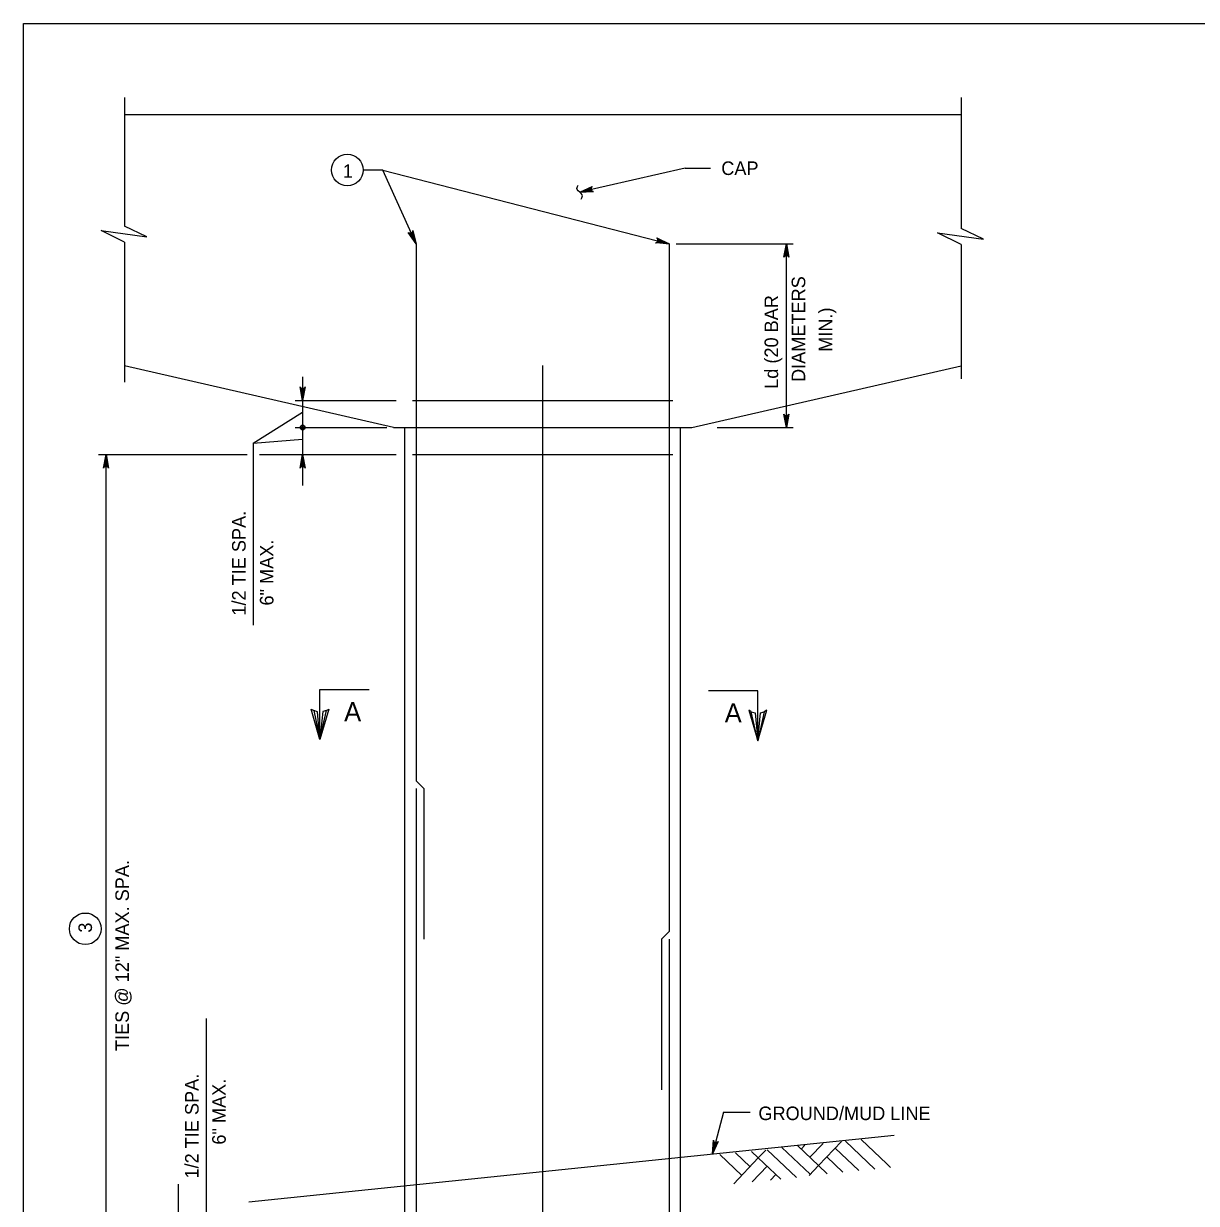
# Model space of a CAD drawing. Extents: x 646165 to 651486, y 296916 to 299292.
# Drawn here: x 649829.6 to 650089.2, y 297234.1 to 297495.3 of the extents above; entities that cross this region are included whole.
import ezdxf

# ---------------------------------------------------------------- set-up
doc = ezdxf.new("R2010")
doc.units = 0
for name, color, linetype in [('1', 7, 'Continuous'), ('2', 7, 'Continuous'), ('50', 7, 'Continuous'), ('51', 7, 'Continuous'), ('52', 7, 'Continuous'), ('53', 7, 'Continuous'), ('54', 7, 'Continuous'), ('56', 7, 'Continuous')]:
    doc.layers.add(name, color=color, linetype=linetype)

msp = doc.modelspace()

# ---------------------------------------------------------------- linework, layer by layer
at = {"layer": '1'}
for p, q in [((649895.19, 297347.84), (649906.11, 297347.84)), ((649895.19, 297336.77), (649895.19, 297347.84)), ((649992.13, 297347.58), (649981.21, 297347.58)), ((649992.13, 297336.51), (649992.13, 297347.58))]:
    msp.add_line(p, q, dxfattribs=at)
for points in [[(649896.66, 297343.19), (649895.81, 297342.96), (649895.19, 297336.77), (649896.66, 297343.19), (649897.18, 297343.52), (649895.19, 297336.77), (649894.63, 297342.95), (649893.8, 297343.18), (649895.19, 297336.77), (649893.24, 297343.52), (649893.8, 297343.18)], [(649990.66, 297342.93), (649991.51, 297342.69), (649992.13, 297336.51), (649990.66, 297342.93), (649990.14, 297343.26), (649992.13, 297336.51), (649992.69, 297342.68), (649993.52, 297342.91), (649992.13, 297336.51), (649994.08, 297343.26), (649993.52, 297342.91)]]:
    msp.add_lwpolyline(points, dxfattribs=at)
at = {"layer": '2'}
for p, q in [((649829.59, 296931.25), (649829.59, 297495.25)), ((649829.59, 297495.25), (650615.59, 297495.25))]:
    msp.add_line(p, q, dxfattribs=at)
at = {"layer": '50'}
msp.add_line((649944.48, 297040.08), (649944.48, 297419.54), dxfattribs=at)
at = {"layer": '51'}
for p, q in [((649851.93, 297475.16), (650037.08, 297475.16)), ((649911.47, 297405.84), (649851.93, 297419.49)), ((649977.48, 297405.84), (650037.08, 297419.51)), ((649911.47, 297405.84), (649977.48, 297405.84)), ((649913.98, 297224.79), (649913.98, 297405.84)), ((649974.98, 297224.79), (649974.98, 297405.84))]:
    msp.add_line(p, q, dxfattribs=at)
at = {"layer": '52'}
for p, q in [((649851.93, 297478.93), (649851.93, 297450.4)), ((650037.08, 297478.93), (650037.08, 297449.87)), ((649909.08, 297462.83), (649904.76, 297462.83)), ((649916.48, 297446.51), (649909.08, 297462.83)), ((649909.08, 297462.83), (649972.48, 297446.51)), ((649976.01, 297463.25), (649952.67, 297457.95)), ((649976.01, 297463.25), (649981.59, 297463.25)), ((649851.93, 297446.9), (649851.93, 297415.92)), ((649974.04, 297446.51), (649999.95, 297446.51)), ((649998.41, 297405.84), (649998.41, 297446.51)), ((650037.08, 297446.37), (650037.08, 297416.64)), ((649891.35, 297417.1), (649891.35, 297392.98)), ((649889.69, 297411.84), (649912.02, 297411.84)), ((649880.4, 297402.4), (649891.35, 297409.26)), ((649889.69, 297405.84), (649910.02, 297405.84)), ((649983.08, 297405.84), (649999.95, 297405.84)), ((649880.4, 297402.4), (649891.35, 297403.24)), ((649880.4, 297402.4), (649880.4, 297362.12)), ((649846.19, 297399.84), (649879.04, 297399.84)), ((649847.85, 297185.79), (649847.85, 297399.84)), ((649881.82, 297399.84), (649912.02, 297399.84)), ((649870.06, 297222.89), (649870.06, 297275.07)), ((649984.5, 297254.34), (649982.04, 297245.07)), ((649984.5, 297254.34), (649990.38, 297254.34)), ((649863.85, 297114.62), (649863.85, 297238.4))]:
    msp.add_line(p, q, dxfattribs=at)
for points in [[(649952.67, 297457.95), (649955.46, 297459.16), (649955.36, 297459.06), (649955.27, 297458.95), (649955.23, 297458.84), (649955.2, 297458.73), (649955.2, 297458.63), (649955.21, 297458.53), (649955.25, 297458.43), (649955.29, 297458.34), (649955.37, 297458.26), (649955.45, 297458.17), (649955.58, 297458.12), (649955.71, 297458.07), (649952.67, 297457.95), (649955.58, 297458.12), (649955.45, 297458.17), (649952.67, 297457.95), (649955.37, 297458.26), (649955.29, 297458.34), (649952.67, 297457.95), (649955.25, 297458.43), (649955.21, 297458.53), (649952.67, 297457.95), (649955.2, 297458.63), (649955.2, 297458.73), (649952.67, 297457.95), (649955.23, 297458.84), (649955.27, 297458.95), (649952.67, 297457.95), (649955.36, 297459.06)], [(649851.93, 297446.9), (649846.74, 297449.44), (649856.89, 297448.06), (649851.93, 297450.42)], [(649916.48, 297446.51), (649914.74, 297449), (649914.86, 297448.93), (649914.98, 297448.85), (649915.09, 297448.84), (649915.21, 297448.83), (649915.31, 297448.86), (649915.4, 297448.88), (649915.49, 297448.94), (649915.57, 297448.99), (649915.64, 297449.09), (649915.71, 297449.19), (649915.73, 297449.32), (649915.76, 297449.46), (649916.48, 297446.51), (649915.73, 297449.32), (649915.71, 297449.19), (649916.48, 297446.51), (649915.64, 297449.09), (649915.57, 297448.99), (649916.48, 297446.51), (649915.49, 297448.94), (649915.4, 297448.88), (649916.48, 297446.51), (649915.31, 297448.86), (649915.21, 297448.83), (649916.48, 297446.51), (649915.09, 297448.84), (649914.98, 297448.85), (649916.48, 297446.51), (649914.86, 297448.93)], [(650037.08, 297446.37), (650031.9, 297448.91), (650042.05, 297447.53), (650037.08, 297449.89)], [(649972.48, 297446.51), (649969.45, 297446.71), (649969.58, 297446.76), (649969.71, 297446.81), (649969.79, 297446.89), (649969.88, 297446.98), (649969.92, 297447.07), (649969.96, 297447.16), (649969.97, 297447.26), (649969.98, 297447.36), (649969.94, 297447.47), (649969.91, 297447.59), (649969.82, 297447.69), (649969.73, 297447.8), (649972.48, 297446.51), (649969.82, 297447.69), (649969.91, 297447.59), (649972.48, 297446.51), (649969.94, 297447.47), (649969.98, 297447.36), (649972.48, 297446.51), (649969.97, 297447.26), (649969.96, 297447.16), (649972.48, 297446.51), (649969.92, 297447.07), (649969.88, 297446.98), (649972.48, 297446.51), (649969.79, 297446.89), (649969.71, 297446.81), (649972.48, 297446.51), (649969.58, 297446.76)], [(649998.41, 297446.51), (649998.97, 297443.53), (649998.89, 297443.64), (649998.81, 297443.76), (649998.71, 297443.82), (649998.61, 297443.88), (649998.51, 297443.9), (649998.41, 297443.91), (649998.31, 297443.9), (649998.21, 297443.88), (649998.11, 297443.82), (649998.01, 297443.76), (649997.93, 297443.64), (649997.85, 297443.53), (649998.41, 297446.51), (649997.93, 297443.64), (649998.01, 297443.76), (649998.41, 297446.51), (649998.11, 297443.82), (649998.21, 297443.88), (649998.41, 297446.51), (649998.31, 297443.9), (649998.41, 297443.91), (649998.41, 297446.51), (649998.51, 297443.9), (649998.61, 297443.88), (649998.41, 297446.51), (649998.71, 297443.82), (649998.81, 297443.76), (649998.41, 297446.51), (649998.89, 297443.64)], [(649891.35, 297411.84), (649890.8, 297414.83), (649890.88, 297414.71), (649890.95, 297414.6), (649891.05, 297414.54), (649891.15, 297414.48), (649891.25, 297414.46), (649891.35, 297414.44), (649891.45, 297414.46), (649891.55, 297414.48), (649891.65, 297414.54), (649891.75, 297414.6), (649891.83, 297414.71), (649891.91, 297414.83), (649891.35, 297411.84), (649891.83, 297414.71), (649891.75, 297414.6), (649891.35, 297411.84), (649891.65, 297414.54), (649891.55, 297414.48), (649891.35, 297411.84), (649891.45, 297414.46), (649891.35, 297414.44), (649891.35, 297411.84), (649891.25, 297414.46), (649891.15, 297414.48), (649891.35, 297411.84), (649891.05, 297414.54), (649890.95, 297414.6), (649891.35, 297411.84), (649890.88, 297414.71)], [(649998.41, 297405.84), (649997.85, 297408.83), (649997.93, 297408.71), (649998.01, 297408.6), (649998.11, 297408.54), (649998.21, 297408.48), (649998.31, 297408.46), (649998.41, 297408.44), (649998.51, 297408.46), (649998.61, 297408.48), (649998.71, 297408.54), (649998.81, 297408.6), (649998.89, 297408.71), (649998.97, 297408.83), (649998.41, 297405.84), (649998.89, 297408.71), (649998.81, 297408.6), (649998.41, 297405.84), (649998.71, 297408.54), (649998.61, 297408.48), (649998.41, 297405.84), (649998.51, 297408.46), (649998.41, 297408.44), (649998.41, 297405.84), (649998.31, 297408.46), (649998.21, 297408.48), (649998.41, 297405.84), (649998.11, 297408.54), (649998.01, 297408.6), (649998.41, 297405.84), (649997.93, 297408.71)], [(649847.85, 297399.84), (649848.41, 297396.86), (649848.33, 297396.98), (649848.25, 297397.09), (649848.15, 297397.15), (649848.05, 297397.21), (649847.95, 297397.23), (649847.85, 297397.24), (649847.75, 297397.23), (649847.65, 297397.21), (649847.55, 297397.15), (649847.45, 297397.09), (649847.37, 297396.98), (649847.3, 297396.86), (649847.85, 297399.84), (649847.37, 297396.98), (649847.45, 297397.09), (649847.85, 297399.84), (649847.55, 297397.15), (649847.65, 297397.21), (649847.85, 297399.84), (649847.75, 297397.23), (649847.85, 297397.24), (649847.85, 297399.84), (649847.95, 297397.23), (649848.05, 297397.21), (649847.85, 297399.84), (649848.15, 297397.15), (649848.25, 297397.09), (649847.85, 297399.84), (649848.33, 297396.98)], [(649891.35, 297399.84), (649891.91, 297396.86), (649891.83, 297396.98), (649891.75, 297397.09), (649891.65, 297397.15), (649891.55, 297397.21), (649891.45, 297397.23), (649891.35, 297397.24), (649891.25, 297397.23), (649891.15, 297397.21), (649891.05, 297397.15), (649890.95, 297397.09), (649890.88, 297396.98), (649890.8, 297396.86), (649891.35, 297399.84), (649890.88, 297396.98), (649890.95, 297397.09), (649891.35, 297399.84), (649891.05, 297397.15), (649891.15, 297397.21), (649891.35, 297399.84), (649891.25, 297397.23), (649891.35, 297397.24), (649891.35, 297399.84), (649891.45, 297397.23), (649891.55, 297397.21), (649891.35, 297399.84), (649891.65, 297397.15), (649891.75, 297397.09), (649891.35, 297399.84), (649891.83, 297396.98)], [(649982.04, 297245.07), (649982.26, 297248.09), (649982.31, 297247.96), (649982.36, 297247.83), (649982.44, 297247.75), (649982.52, 297247.67), (649982.62, 297247.62), (649982.71, 297247.58), (649982.81, 297247.57), (649982.91, 297247.56), (649983.02, 297247.59), (649983.13, 297247.63), (649983.24, 297247.72), (649983.35, 297247.81), (649982.04, 297245.07), (649983.24, 297247.72), (649983.13, 297247.63), (649982.04, 297245.07), (649983.02, 297247.59), (649982.91, 297247.56), (649982.04, 297245.07), (649982.81, 297247.57), (649982.71, 297247.58), (649982.04, 297245.07), (649982.62, 297247.62), (649982.52, 297247.67), (649982.04, 297245.07), (649982.44, 297247.75), (649982.36, 297247.83), (649982.04, 297245.07), (649982.31, 297247.96)]]:
    msp.add_lwpolyline(points, dxfattribs=at)
for centre, radius in [((649901.26, 297462.83), 3.5), ((649891.35, 297405.84), 0.533), ((649891.35, 297405.84), 0.267), ((649843.23, 297294.89), 3.5)]:
    msp.add_circle(centre, radius, dxfattribs=at)
msp.add_spline([(649952.99, 297456.42), (649953.25, 297457.37), (649952.09, 297458.54), (649952.31, 297459.46)], degree=3, dxfattribs=at)
at = {"layer": '54'}
for p, q in [((649916.48, 297446.51), (649916.48, 297327.61)), ((649972.48, 297446.51), (649972.48, 297294.28)), ((649915.64, 297411.84), (649973.31, 297411.84)), ((649915.64, 297399.84), (649973.31, 297399.84)), ((649918.14, 297325.94), (649916.48, 297327.61)), ((649916.48, 297325.94), (649916.48, 297184.12)), ((649918.14, 297325.94), (649918.14, 297292.61)), ((649970.81, 297292.61), (649972.48, 297294.28)), ((649970.81, 297292.61), (649970.81, 297259.28)), ((649972.48, 297292.61), (649972.48, 297184.12))]:
    msp.add_line(p, q, dxfattribs=at)
at = {"layer": '56'}
for p, q in [((649879.41, 297234.46), (650022.3, 297249.23)), ((650005.55, 297242.48), (650010.59, 297247.8)), ((650017.98, 297241.72), (650011.47, 297247.89)), ((650020.63, 297242.89), (650014.99, 297248.23)), ((649990.37, 297242.24), (649987.18, 297245.27)), ((649992.21, 297244.18), (649990.69, 297245.61)), ((649992.21, 297244.18), (649993.86, 297245.93)), ((650000.68, 297239.82), (649994.2, 297245.96)), ((650003.71, 297240.55), (649997.43, 297246.5)), ((650005.55, 297242.48), (650000.94, 297246.85)), ((650001.67, 297246.15), (650002.48, 297247)), ((650003.61, 297244.32), (650006.53, 297247.4)), ((650014.47, 297241.38), (650009.22, 297246.35)), ((649988.54, 297240.31), (649983.67, 297244.92)), ((649986.79, 297238.46), (649992.21, 297244.18)), ((649997.17, 297239.48), (649992.21, 297244.18)), ((650010.95, 297241.03), (650007.38, 297244.42)), ((650021.5, 297242.06), (650020.63, 297242.89)), ((649990.84, 297238.86), (649994.14, 297242.35)), ((649994.89, 297239.26), (649996.08, 297240.51)), ((650003.48, 297240.3), (650005.55, 297242.48)), ((650007.44, 297240.69), (650005.55, 297242.48))]:
    msp.add_line(p, q, dxfattribs=at)

# ---------------------------------------------------------------- texts
at = {"layer": '1'}
for p in [(649900.54, 297340.83), (649984.77, 297340.56)]:
    msp.add_text('A', height=4.23, dxfattribs=at).set_placement(p)
at = {"layer": '53'}
for s, p in [('CAP', (649984.01, 297461.74)), ('1', (649900.27, 297461.12)), ('GROUND/MUD LINE', (649992.23, 297252.55))]:
    msp.add_text(s, height=3, dxfattribs=at).set_placement(p)
for s, p in [('DIAMETERS', (650002.59, 297415.93)), ('Ld (20 BAR ', (649996.59, 297414.42)), ('MIN.)', (650008.59, 297422.61)), ('1/2 TIE SPA.', (649878.74, 297364.22)), ('  6" MAX.', (649884.89, 297364.22)), ('TIES @ 12" MAX. SPA.', (649852.91, 297267.83)), ('3', (649844.73, 297294.04)), ('1/2 TIE SPA.', (649868.33, 297239.62)), ('6" MAX.', (649874.33, 297247.12))]:
    msp.add_text(s, height=3, rotation=90, dxfattribs=at).set_placement(p)

doc.saveas('drawing.dxf')
